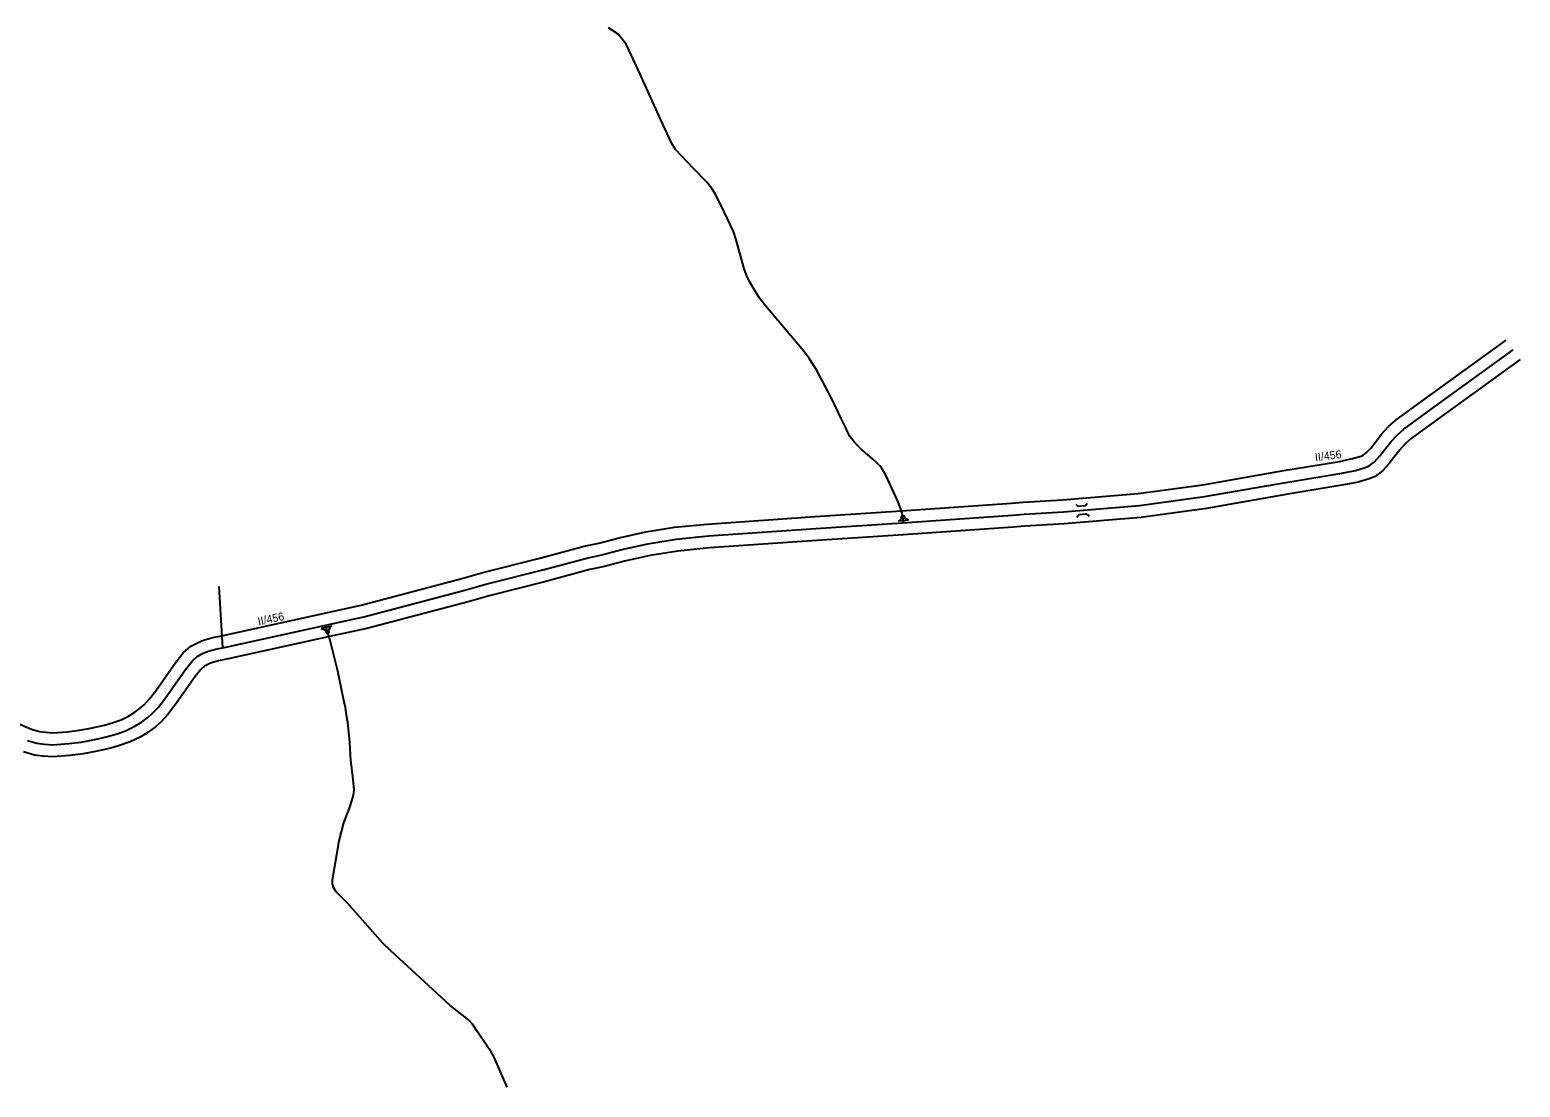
# Model space of a CAD drawing. Extents: x -546703 to -534152, y -1046534 to -1035676.
# Drawn here: x -542103 to -540241, y -1040412 to -1039091 of the extents above; entities that cross this region are included whole.
import ezdxf

# ---------------------------------------------------------------- set-up
doc = ezdxf.new("R2010")
doc.units = 0
for name, color, linetype in [('Vrstva 11', 7, 'Continuous'), ('Vrstva 17', 7, 'Continuous'), ('Vrstva 3', 7, 'Continuous'), ('Vrstva 7', 7, 'Continuous'), ('Vrstva 8', 7, 'Continuous')]:
    doc.layers.add(name, color=color, linetype=linetype)

msp = doc.modelspace()

# ---------------------------------------------------------------- linework, layer by layer
at = {"layer": 'Vrstva 11'}
for points in [[(-541011.3, -1039706.6), (-541012.6, -1039699.2), (-541013.4, -1039694.7), (-541015.3, -1039688.3), (-541018.9, -1039679.8), (-541033.9, -1039647.1), (-541038.7, -1039638.7), (-541041.1, -1039635.7), (-541045.3, -1039631.6), (-541050.1, -1039627.3), (-541056.3, -1039621.7), (-541064.1, -1039615.1), (-541069.9, -1039609.5), (-541073.5, -1039605.7), (-541078.1, -1039599.4), (-541080.8, -1039594.8), (-541084.3, -1039587.2), (-541089.6, -1039576.3), (-541093.4, -1039568.4), (-541095.7, -1039563.3), (-541101.1, -1039551.8), (-541120.4, -1039515.5), (-541129.7, -1039501.6), (-541136.5, -1039492), (-541183.9, -1039435.9), (-541191.6, -1039426.1), (-541199.8, -1039412.5), (-541204.6, -1039404.7), (-541207.8, -1039397.6), (-541210.9, -1039389.4), (-541220.7, -1039353.2), (-541224.2, -1039342.9), (-541235.4, -1039319.2), (-541243.7, -1039302.2), (-541246.9, -1039296), (-541251.1, -1039289.2), (-541257.6, -1039281.3), (-541273.9, -1039264), (-541296.7, -1039240.6), (-541301, -1039233.1), (-541309.8, -1039214.4), (-541315.3, -1039202.7), (-541342.8, -1039141.9), (-541358.1, -1039108.7), (-541364.9, -1039100.5), (-541368.4, -1039096.4), (-541380.3, -1039088.3)], [(-541506.9, -1040411.7), (-541523.7, -1040373.4), (-541526.9, -1040367.5), (-541530.9, -1040361.7), (-541543.8, -1040342.6), (-541550.4, -1040332.9), (-541554.6, -1040328.3), (-541557.5, -1040325.8), (-541578.7, -1040309.4), (-541652.5, -1040241.5), (-541662.1, -1040231.9), (-541706.6, -1040181.9), (-541709.6, -1040178.6), (-541720.5, -1040167.6), (-541723.4, -1040163), (-541725.2, -1040157.5), (-541725.3, -1040152.7), (-541717, -1040103.8), (-541710.9, -1040081.6), (-541704.1, -1040063), (-541700.5, -1040052.6), (-541698.9, -1040047.1), (-541698, -1040040.3), (-541699.9, -1040023.4), (-541702.2, -1040003.8), (-541703.6, -1039981), (-541704.6, -1039968.4), (-541706.1, -1039956.1), (-541707.5, -1039947.1), (-541709, -1039937.4), (-541710.9, -1039928.5), (-541718.7, -1039891.9), (-541728.7, -1039852.1), (-541733.8, -1039834.6)]]:
    msp.add_lwpolyline(points, dxfattribs=at)
for points in [[(-541014.4, -1039698.9), (-541014.4, -1039700.7), (-541014.7, -1039701.8), (-541015.4, -1039702.8), (-541017.4, -1039704.1), (-541013.3, -1039703.8), (-541005.7, -1039703.2), (-541008, -1039702.3), (-541009.4, -1039701.3), (-541010.4, -1039699.7), (-541011, -1039698.1)], [(-541739.3, -1039838.8), (-541736.7, -1039839.5), (-541734.8, -1039840.6), (-541733.7, -1039842.1), (-541732.7, -1039844.5), (-541729.3, -1039843.7), (-541729.6, -1039841.5), (-541729.2, -1039839.4), (-541728, -1039837.4), (-541726.4, -1039836)]]:
    msp.add_lwpolyline(points, close=True, dxfattribs=at)
at = {"layer": 'Vrstva 17'}
for points in [[(-542119.9, -1039956.4), (-542101.3, -1039964.4), (-542091.3, -1039967.4), (-542083.4, -1039968.4), (-542074.6, -1039969.1), (-542056.3, -1039967.7), (-542041.5, -1039965.8), (-542027.1, -1039963.1), (-542018.2, -1039961.2), (-542010.3, -1039959.3), (-541999.1, -1039956), (-541989.5, -1039952.7), (-541980.2, -1039948.1), (-541972.2, -1039943.2), (-541965.5, -1039938.4), (-541960.5, -1039933.9), (-541953.9, -1039926.8), (-541946.1, -1039916.5), (-541920.9, -1039880.8), (-541911.7, -1039869.1), (-541902.2, -1039860.9), (-541893.1, -1039856.1), (-541886.2, -1039853.2), (-541874.9, -1039850.1), (-541861.8, -1039847.3), (-541729.4, -1039818.2), (-541689.5, -1039809.5), (-541563.7, -1039776.5), (-541537.3, -1039768.8), (-541466.3, -1039751.1), (-541410.9, -1039736.1), (-541392.2, -1039732), (-541367.1, -1039725.6), (-541333.8, -1039718.1), (-541297.7, -1039712.3), (-541256.6, -1039708.3), (-541122, -1039698.9), (-541014.1, -1039691.8), (-540876.8, -1039682.2), (-540862.1, -1039681), (-540812.8, -1039678.1), (-540718.5, -1039670.2), (-540637.6, -1039659.1), (-540536.2, -1039641.5), (-540466.8, -1039630), (-540450.6, -1039626.6), (-540439.8, -1039623.5), (-540437.2, -1039622.4), (-540433.3, -1039619.5), (-540427.6, -1039613.4), (-540414.2, -1039596.1), (-540405.5, -1039586.6), (-540396.1, -1039578), (-540356.4, -1039549.4), (-540258.6, -1039478.6)], [(-540241, -1039502.9), (-540338.8, -1039573.7), (-540377.2, -1039601.3), (-540384.3, -1039607.8), (-540391.2, -1039615.4), (-540404.7, -1039632.8), (-540413.1, -1039641.9), (-540422.3, -1039648.7), (-540429.9, -1039651.9), (-540443.3, -1039655.8), (-540461.3, -1039659.5), (-540531.2, -1039671.1), (-540633, -1039688.7), (-540715.2, -1039700), (-540810.7, -1039708), (-540860, -1039710.9), (-540874.4, -1039712.1), (-541012.1, -1039721.7), (-541120, -1039728.9), (-541254.1, -1039738.2), (-541293.8, -1039742.1), (-541328.1, -1039747.6), (-541360.1, -1039754.8), (-541385.3, -1039761.2), (-541403.7, -1039765.2), (-541458.7, -1039780.1), (-541529.4, -1039797.8), (-541555.7, -1039805.4), (-541682.5, -1039838.6), (-541723, -1039847.5), (-541855.5, -1039876.6), (-541867.8, -1039879.2), (-541876.4, -1039881.6), (-541880.3, -1039883.3), (-541885.2, -1039885.8), (-541889.8, -1039889.9), (-541896.8, -1039898.8), (-541921.8, -1039934.2), (-541930.9, -1039946.2), (-541939.4, -1039955.3), (-541946.6, -1039961.7), (-541955.6, -1039968.2), (-541965.7, -1039974.4), (-541978, -1039980.5), (-541990, -1039984.5), (-542002.4, -1039988.3), (-542011.6, -1039990.5), (-542021.3, -1039992.5), (-542036.9, -1039995.4), (-542053.3, -1039997.5), (-542074.5, -1039999.2), (-542086.6, -1039998.3), (-542097.6, -1039996.8), (-542111.5, -1039992.7)]]:
    msp.add_lwpolyline(points, dxfattribs=at)
at = {"layer": 'Vrstva 3'}
msp.add_lwpolyline([(-542106.4, -1039978.5), (-542094.5, -1039982.1), (-542085, -1039983.4), (-542074.6, -1039984.2), (-542054.8, -1039982.6), (-542039.2, -1039980.6), (-542024.2, -1039977.8), (-542014.9, -1039975.9), (-542006.4, -1039973.8), (-541994.5, -1039970.3), (-541983.7, -1039966.6), (-541972.9, -1039961.2), (-541963.9, -1039955.7), (-541956, -1039950), (-541950, -1039944.6), (-541942.4, -1039936.5), (-541934, -1039925.3), (-541908.9, -1039889.8), (-541900.7, -1039879.5), (-541893.7, -1039873.4), (-541886.7, -1039869.7), (-541881.3, -1039867.4), (-541871.4, -1039864.7), (-541858.6, -1039861.9), (-541726.2, -1039832.9), (-541686, -1039824), (-541559.7, -1039791), (-541533.4, -1039783.3), (-541462.5, -1039765.6), (-541407.3, -1039750.7), (-541388.7, -1039746.6), (-541363.6, -1039740.2), (-541331, -1039732.9), (-541295.8, -1039727.2), (-541255.4, -1039723.2), (-541121, -1039713.9), (-541013.1, -1039706.8), (-540875.6, -1039697.2), (-540861, -1039695.9), (-540811.7, -1039693.1), (-540716.8, -1039685.1), (-540635.3, -1039673.9), (-540533.7, -1039656.3), (-540464, -1039644.7), (-540446.9, -1039641.2), (-540434.9, -1039637.7), (-540429.7, -1039635.6), (-540423.2, -1039630.7), (-540416.2, -1039623.1), (-540402.7, -1039605.8), (-540394.9, -1039597.2), (-540386.6, -1039589.6), (-540347.6, -1039561.5), (-540249.8, -1039490.7)], dxfattribs=at)
at = {"layer": 'Vrstva 7'}
msp.add_line((-541867.1, -1039786.2), (-541862.6, -1039862.8), dxfattribs=at)
at = {"layer": 'Vrstva 8'}
for points in [[(-540796.3, -1039683.3), (-540793.9, -1039685.8), (-540784, -1039685.1), (-540782.2, -1039682.2)], [(-540795.2, -1039699.7), (-540792.5, -1039696.4), (-540783.8, -1039695.6), (-540779.7, -1039698.2)]]:
    msp.add_lwpolyline(points, dxfattribs=at)

# ---------------------------------------------------------------- texts
at = {"layer": 'Vrstva 3'}
for rotation, p in [(7.1138, (-540496.9, -1039629.9)), (12.1023, (-541817.5, -1039835))]:
    msp.add_text('II/456', height=10, rotation=rotation, dxfattribs=at).set_placement(p)

doc.saveas('drawing.dxf')
